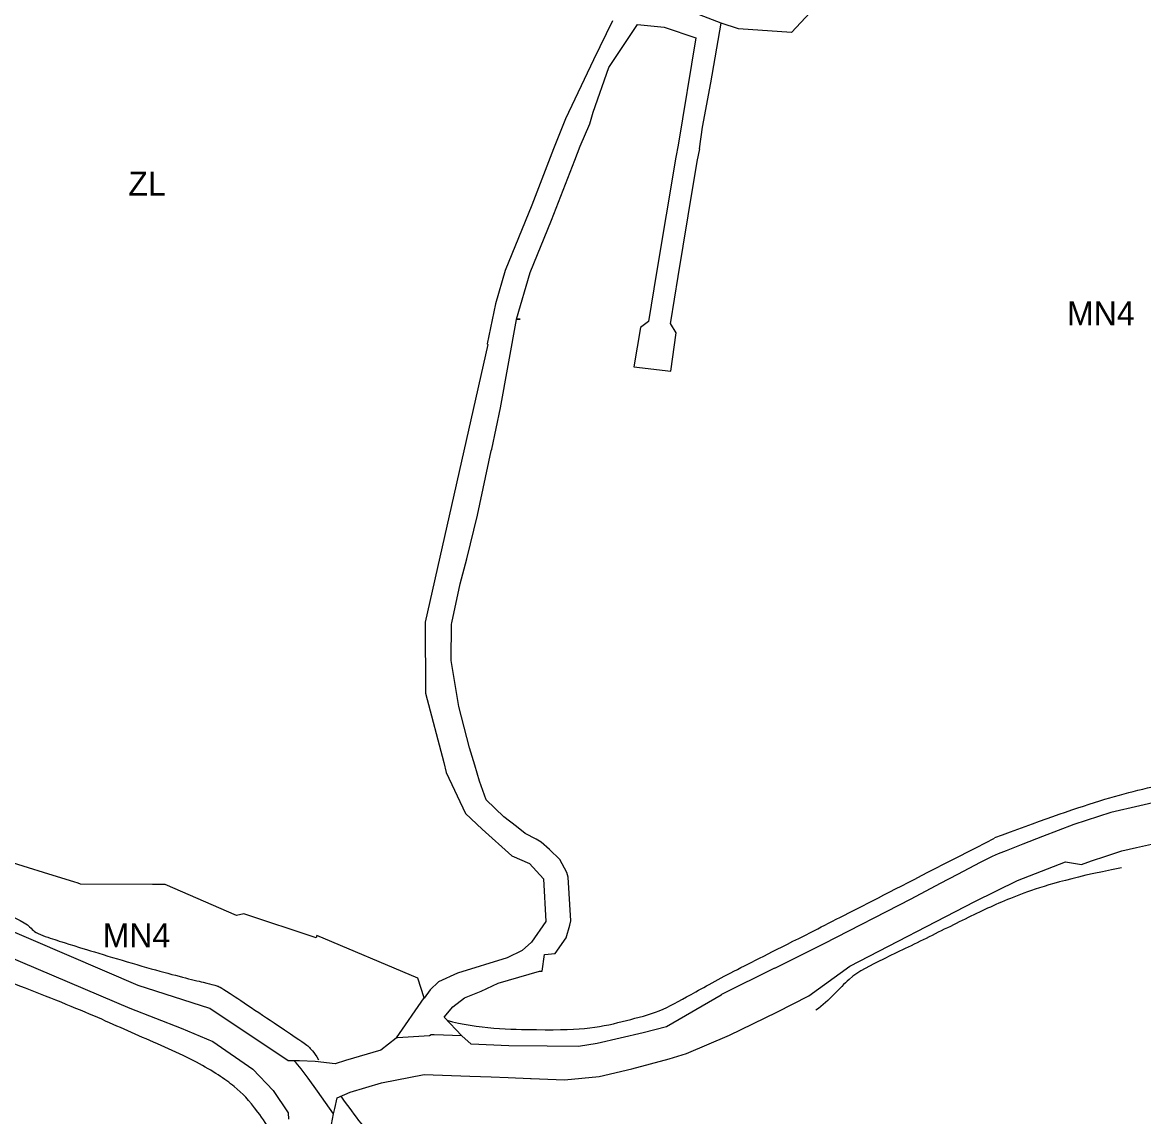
# Model space of a CAD drawing. Extents: x 7413438 to 7416393, y 5541665 to 5544118.
# Drawn here: x 7414980.3 to 7415261.6, y 5542694.9 to 5542969.5 of the extents above; entities that cross this region are included whole.
import ezdxf

# ---------------------------------------------------------------- set-up
doc = ezdxf.new("R2010")
doc.units = 0
for name, color, linetype in [('linie_rozgraniczajace', 7, 'Continuous'), ('linie_zabudowy_nieprzekraczalne', 7, 'Continuous'), ('oznaczenia_przeznaczen', 7, 'Continuous')]:
    doc.layers.add(name, color=color, linetype=linetype)

msp = doc.modelspace()

# ---------------------------------------------------------------- linework, layer by layer
at = {"layer": 'linie_rozgraniczajace'}
for p, q in [((7415185.78, 5542980.52), (7415173.2, 5542967.04)), ((7415155.59, 5542969.34), (7415150.15, 5542971.47)), ((7415128.31, 5542969.98), (7415123.55, 5542960.19)), ((7415127.37, 5542958.24), (7415134.6, 5542969.01)), ((7415134.6, 5542969.01), (7415141.25, 5542968.32)), ((7415153.02, 5542954.4), (7415155.59, 5542969.34)), ((7415159.9, 5542967.95), (7415155.59, 5542969.34)), ((7415141.25, 5542968.32), (7415149.22, 5542965.64)), ((7415149.22, 5542965.64), (7415144.76, 5542938.77)), ((7415173.2, 5542967.04), (7415159.9, 5542967.95)), ((7415123.55, 5542960.19), (7415116.57, 5542945.38)), ((7415123.44, 5542947.01), (7415127.37, 5542958.24)), ((7415150.88, 5542943.24), (7415153.02, 5542954.4)), ((7415122.65, 5542944.09), (7415123.44, 5542947.01)), ((7415116.57, 5542945.38), (7415113.51, 5542937.85)), ((7415120.17, 5542938.48), (7415122.65, 5542944.09)), ((7415150.12, 5542937.86), (7415150.88, 5542943.24)), ((7415113.51, 5542937.85), (7415108.05, 5542923.69)), ((7415118.84, 5542934.98), (7415120.17, 5542938.48)), ((7415144.76, 5542938.77), (7415144.25, 5542935.7)), ((7415149.58, 5542934.63), (7415150.2, 5542937.82)), ((7415150.22, 5542937.84), (7415150.12, 5542937.86)), ((7415150.2, 5542937.82), (7415150.22, 5542937.84)), ((7415112.99, 5542919.91), (7415118.84, 5542934.98)), ((7415144.25, 5542935.7), (7415139.39, 5542906.76)), ((7415147.33, 5542920.97), (7415149.59, 5542934.62)), ((7415149.59, 5542934.62), (7415149.58, 5542934.63)), ((7415108.05, 5542923.69), (7415101.43, 5542907.3)), ((7415144.82, 5542905.8), (7415147.33, 5542920.97)), ((7415107.7, 5542906.8), (7415112.99, 5542919.91)), ((7415101.43, 5542907.3), (7415098.99, 5542898.92)), ((7415104.26, 5542895.09), (7415107.7, 5542906.8)), ((7415139.39, 5542906.76), (7415137.32, 5542894.45)), ((7415142.93, 5542894.41), (7415144.82, 5542905.8)), ((7415098.99, 5542898.92), (7415096.89, 5542888.86)), ((7415100.21, 5542872.85), (7415104.23, 5542894.97)), ((7415104.23, 5542895.05), (7415104.26, 5542895.09)), ((7415105.14, 5542895.08), (7415104.23, 5542895.05)), ((7415104.23, 5542894.97), (7415105.14, 5542895.06)), ((7415105.14, 5542895.06), (7415105.14, 5542895.08)), ((7415135.31, 5542892.99), (7415133.64, 5542883.09)), ((7415137.32, 5542894.45), (7415135.31, 5542892.99)), ((7415142.85, 5542893.94), (7415142.93, 5542894.41)), ((7415144.27, 5542891.61), (7415142.85, 5542893.94)), ((7415142.97, 5542882), (7415144.27, 5542891.61)), ((7415097.01, 5542888.67), (7415081.3, 5542819.03)), ((7415096.89, 5542888.86), (7415097.01, 5542888.67)), ((7415133.64, 5542883.09), (7415142.97, 5542882)), ((7415098.01, 5542862.47), (7415100.21, 5542872.85)), ((7415094.45, 5542845.85), (7415097.92, 5542862.04)), ((7415097.92, 5542862.04), (7415098.01, 5542862.47)), ((7415091.78, 5542834.95), (7415094.45, 5542845.85)), ((7415090.12, 5542828.62), (7415091.79, 5542834.94)), ((7415091.79, 5542834.94), (7415091.78, 5542834.95)), ((7415087.98, 5542818.82), (7415090.12, 5542828.62)), ((7415081.3, 5542819.03), (7415081.37, 5542801.2)), ((7415087.83, 5542809.35), (7415087.93, 5542818.55)), ((7415087.93, 5542818.55), (7415087.98, 5542818.82)), ((7415089.79, 5542797.83), (7415087.83, 5542809.35)), ((7415081.37, 5542801.2), (7415085.97, 5542783.76)), ((7415092.43, 5542787.44), (7415089.79, 5542797.83)), ((7415093.75, 5542783.12), (7415092.43, 5542787.44)), ((7415085.97, 5542783.76), (7415086.62, 5542781.3)), ((7415094.97, 5542779.1), (7415093.75, 5542783.12)), ((7415086.62, 5542781.3), (7415091.45, 5542770.96)), ((7415096.66, 5542774.41), (7415094.97, 5542779.1)), ((7415101.02, 5542770.14), (7415096.66, 5542774.41)), ((7415277.94, 5542776.84), (7415253.36, 5542771.27)), ((7415091.45, 5542770.96), (7415095.65, 5542767.04)), ((7415104.2, 5542767.69), (7415101.02, 5542770.14)), ((7415253.36, 5542771.27), (7415244.08, 5542768.23)), ((7415095.65, 5542767.04), (7415103.08, 5542760.33)), ((7415106.44, 5542765.96), (7415104.2, 5542767.69)), ((7415109.14, 5542764.53), (7415106.44, 5542765.96)), ((7415244.08, 5542768.23), (7415236.24, 5542765.19)), ((7415110.46, 5542763.83), (7415109.14, 5542764.53)), ((7415112.53, 5542761.97), (7415110.46, 5542763.83)), ((7415231.3, 5542763.27), (7415227.06, 5542761.63)), ((7415236.24, 5542765.19), (7415231.3, 5542763.27)), ((7415259.77, 5542762.49), (7415263.52, 5542763.31)), ((7414986.87, 5542755.76), (7414967.03, 5542761.91)), ((7415103.08, 5542760.33), (7415107.52, 5542758.48)), ((7415115.12, 5542759.42), (7415112.53, 5542761.97)), ((7415225.12, 5542760.84), (7415223.55, 5542760.22)), ((7415225.78, 5542761.1), (7415225.12, 5542760.84)), ((7415227.06, 5542761.61), (7415225.78, 5542761.1)), ((7415227.06, 5542761.63), (7415227.06, 5542761.61)), ((7415248.48, 5542759.07), (7415252.08, 5542760.3)), ((7415252.08, 5542760.3), (7415256.09, 5542761.59)), ((7415256.09, 5542761.59), (7415259.77, 5542762.49)), ((7415107.52, 5542758.48), (7415111.03, 5542754.63)), ((7415116.9, 5542756.17), (7415115.12, 5542759.42)), ((7415220.59, 5542758.68), (7415214.9, 5542755.72)), ((7415223.55, 5542760.22), (7415220.59, 5542758.68)), ((7415229.96, 5542754.18), (7415241.99, 5542758.83)), ((7415241.99, 5542758.83), (7415245.97, 5542758.23)), ((7415245.97, 5542758.23), (7415248.48, 5542759.07)), ((7414993.14, 5542753.81), (7414986.87, 5542755.76)), ((7415111.03, 5542754.63), (7415111.63, 5542743.84)), ((7415117.19, 5542755.04), (7415116.9, 5542756.17)), ((7415117.88, 5542744.02), (7415117.19, 5542755.04)), ((7415214.9, 5542755.72), (7415210.52, 5542753.44)), ((7415214.9, 5542755.72), (7415214.9, 5542755.72)), ((7414994.22, 5542753.48), (7414993.14, 5542753.81)), ((7414994.83, 5542753.28), (7414994.22, 5542753.48)), ((7415012.92, 5542753.17), (7414994.83, 5542753.28)), ((7415016.1, 5542753.15), (7415012.92, 5542753.17)), ((7415033.95, 5542745.35), (7415016.1, 5542753.15)), ((7415210.52, 5542753.44), (7415203.14, 5542749.45)), ((7415219.21, 5542748.94), (7415229.96, 5542754.18)), ((7415009.32, 5542727.85), (7414958.64, 5542749.51)), ((7415203.14, 5542749.49), (7415181.33, 5542738.3)), ((7415203.14, 5542749.45), (7415203.14, 5542749.49)), ((7415187.9, 5542732.66), (7415219.21, 5542748.94)), ((7415035.82, 5542745.84), (7415033.95, 5542745.35)), ((7415053.98, 5542739.77), (7415035.82, 5542745.84)), ((7415111.63, 5542743.84), (7415107.98, 5542738.68)), ((7415117.59, 5542742.93), (7415117.88, 5542744.02)), ((7415116.72, 5542739.76), (7415117.59, 5542742.93)), ((7415054.13, 5542740.34), (7415053.98, 5542739.77)), ((7415079.48, 5542729.7), (7415054.13, 5542740.34)), ((7415107.98, 5542738.68), (7415105.66, 5542736.59)), ((7415113.9, 5542735.86), (7415116.72, 5542739.76)), ((7415181.33, 5542738.27), (7415169, 5542732.08)), ((7415181.33, 5542738.3), (7415181.33, 5542738.27)), ((7414976.34, 5542735.27), (7415007.22, 5542722.13)), ((7415105.66, 5542736.59), (7415101.88, 5542734.73)), ((7415110.69, 5542731.43), (7415111.26, 5542735.64)), ((7415111.26, 5542735.64), (7415113.9, 5542735.86)), ((7415101.88, 5542734.73), (7415089.47, 5542730.9)), ((7415169, 5542732.14), (7415155.67, 5542725.54)), ((7415169, 5542732.08), (7415169, 5542732.14)), ((7415177.56, 5542725.2), (7415187.9, 5542732.66)), ((7415081.05, 5542724.71), (7415079.48, 5542729.7)), ((7415089.47, 5542730.9), (7415084.7, 5542728.72)), ((7415099.67, 5542728.37), (7415110.01, 5542731.4)), ((7415110.01, 5542731.4), (7415110.69, 5542731.43)), ((7415027.31, 5542722.08), (7415009.32, 5542727.85)), ((7415082.55, 5542726.74), (7415081.07, 5542724.67)), ((7415084.7, 5542728.72), (7415082.55, 5542726.74)), ((7415095.33, 5542726.36), (7415099.67, 5542728.37)), ((7415074.14, 5542714.71), (7415081.05, 5542724.71)), ((7415081.07, 5542724.67), (7415081.05, 5542724.71)), ((7415088.22, 5542722.48), (7415091.2, 5542724.71)), ((7415091.2, 5542724.71), (7415095.33, 5542726.36)), ((7415155.59, 5542725.42), (7415141.89, 5542717.46)), ((7415155.67, 5542725.54), (7415155.59, 5542725.5)), ((7415155.59, 5542725.5), (7415155.59, 5542725.42)), ((7415169.52, 5542721.15), (7415177.56, 5542725.2)), ((7415007.22, 5542722.13), (7415020.11, 5542717.14)), ((7415046.98, 5542708.87), (7415027.31, 5542722.08)), ((7415086.05, 5542719.85), (7415088.22, 5542722.48)), ((7415157.68, 5542715.32), (7415169.52, 5542721.15)), ((7415090.55, 5542715.15), (7415086.05, 5542719.85)), ((7415020.11, 5542717.14), (7415028.01, 5542713.75)), ((7415082.8, 5542715.44), (7415082.41, 5542715.21)), ((7415083.61, 5542715.41), (7415082.8, 5542715.44)), ((7415090.55, 5542715.15), (7415083.61, 5542715.41)), ((7415136.01, 5542715.94), (7415124.51, 5542713.25)), ((7415141.89, 5542717.46), (7415136.01, 5542715.94)), ((7415146.92, 5542710.77), (7415157.68, 5542715.32)), ((7415028.01, 5542713.75), (7415038.11, 5542706.82)), ((7415074.08, 5542714.63), (7415070.21, 5542711.62)), ((7415074.14, 5542714.71), (7415074.08, 5542714.63)), ((7415074.36, 5542714.7), (7415074.14, 5542714.71)), ((7415082.41, 5542715.21), (7415074.36, 5542714.7)), ((7415092.85, 5542713.07), (7415090.55, 5542715.15)), ((7415102.35, 5542712.71), (7415092.85, 5542713.07)), ((7415111.95, 5542712.57), (7415102.35, 5542712.71)), ((7415119.82, 5542712.52), (7415111.95, 5542712.57)), ((7415124.51, 5542713.25), (7415119.82, 5542712.52)), ((7415070.21, 5542711.62), (7415061.36, 5542709.02)), ((7415142.55, 5542709.44), (7415146.92, 5542710.77)), ((7415038.11, 5542706.82), (7415043.19, 5542701.48)), ((7415048.45, 5542708.94), (7415046.98, 5542708.87)), ((7415048.97, 5542708.37), (7415048.45, 5542708.94)), ((7415049.74, 5542708.88), (7415048.45, 5542708.94)), ((7415050.23, 5542706.91), (7415048.97, 5542708.37)), ((7415049.75, 5542708.87), (7415049.74, 5542708.88)), ((7415053.7, 5542708.74), (7415049.75, 5542708.87)), ((7415051.97, 5542704.57), (7415050.23, 5542706.91)), ((7415058.75, 5542708.12), (7415053.7, 5542708.74)), ((7415061.36, 5542709.02), (7415058.75, 5542708.12)), ((7415125.01, 5542705.01), (7415133.14, 5542706.93)), ((7415133.14, 5542706.93), (7415142.58, 5542709.4)), ((7415142.58, 5542709.4), (7415142.55, 5542709.44)), ((7415054.3, 5542701.33), (7415051.97, 5542704.57)), ((7415070.34, 5542703.4), (7415081.04, 5542705.5)), ((7415081.04, 5542705.5), (7415092.55, 5542705.07)), ((7415092.55, 5542705.07), (7415097.91, 5542704.87)), ((7415097.91, 5542704.87), (7415102.18, 5542704.71)), ((7415102.18, 5542704.71), (7415107.75, 5542704.5)), ((7415107.75, 5542704.5), (7415107.95, 5542704.5)), ((7415107.95, 5542704.5), (7415116.29, 5542704.18)), ((7415116.29, 5542704.18), (7415125.01, 5542705.01)), ((7415043.19, 5542701.48), (7415046.96, 5542695.83)), ((7415058.35, 5542695.59), (7415054.3, 5542701.33)), ((7415062.46, 5542701.01), (7415070.34, 5542703.4)), ((7415058.65, 5542696.98), (7415059.22, 5542699.64)), ((7415059.22, 5542699.64), (7415062.46, 5542701.01)), ((7415046.96, 5542695.83), (7415047.02, 5542694.24)), ((7415057.85, 5542692.95), (7415058.35, 5542695.59)), ((7415058.35, 5542695.59), (7415058.65, 5542696.98))]:
    msp.add_line(p, q, dxfattribs=at)
at = {"layer": 'linie_zabudowy_nieprzekraczalne'}
for points in [[(7415224.24, 5542764.93), (7415234.87, 5542768.93), (7415252.45, 5542775.15), (7415267.62, 5542778.59), (7415300.4, 5542786.16), (7415306.31, 5542787.89), (7415321.64, 5542794.04), (7415341.99, 5542803.09), (7415373.83, 5542816.66), (7415358.63, 5542848.96), (7415349.07, 5542869.68), (7415324.44, 5542923.07), (7415321.98, 5542928.69), (7415321.86, 5542932.66), (7415323.07, 5542937.93), (7415326.67, 5542952.06), (7415325.97, 5542960.66), (7415326.79, 5542972.64), (7415328.33, 5542984.95), (7415330.18, 5542999.75), (7415333.24, 5543013.48), (7415339.07, 5543034.4), (7415348.26, 5543068.35), (7415353.84, 5543088.85), (7415355.35, 5543096.84)], [(7415046.04, 5542685.6), (7415044.89, 5542688.05), (7415038.46, 5542697.69), (7415034.17, 5542702.2), (7415025.08, 5542708.44), (7415009, 5542715.33), (7414995.57, 5542721.52), (7414970.94, 5542731.05), (7414970.88, 5542731.08), (7414970.52, 5542731.25), (7414970.35, 5542731.34), (7414938.93, 5542744.38), (7414938.9, 5542744.39), (7414938.71, 5542744.46), (7414901.8, 5542759.46), (7414901.63, 5542759.53), (7414901.27, 5542759.7), (7414900.93, 5542759.89), (7414900.6, 5542760.11), (7414900.45, 5542760.22), (7414898.5, 5542761.69), (7414898.34, 5542761.82), (7414898.1, 5542762.02), (7414893.84, 5542765.85), (7414883.77, 5542771.83), (7414883.71, 5542771.87), (7414883.61, 5542771.93), (7414880.89, 5542773.67), (7414878.59, 5542776.46), (7414860.73, 5542786.52), (7414855.46, 5542791.34), (7414852.65, 5542792.67), (7414844.32, 5542798.84), (7414832.02, 5542808.01), (7414822.28, 5542811.7), (7414810.95, 5542816.79), (7414794.96, 5542824.01), (7414775.51, 5542832.34), (7414755.97, 5542839.09), (7414752.31, 5542840.07), (7414750.38, 5542840.58), (7414740.26, 5542842.54), (7414740.13, 5542842.57), (7414739.26, 5542842.76)], [(7414894.41, 5542785.03), (7414903.96, 5542777.18), (7414916.18, 5542770.19), (7414940, 5542760.98), (7414955.95, 5542754.25), (7414982.82, 5542743.43), (7414982.18, 5542741.35), (7414988.41, 5542739.33), (7414991.26, 5542738.4), (7415014.09, 5542731.42), (7415027.59, 5542728.16), (7415029.35, 5542727.68), (7415030.41, 5542727.17), (7415050.65, 5542713.59), (7415051.96, 5542712.68), (7415053.26, 5542711.22), (7415054.57, 5542709.16)], [(7415086.74, 5542719.08), (7415094.43, 5542716.98), (7415111.6, 5542716.62), (7415123.06, 5542716.83), (7415131.88, 5542719.06), (7415140.33, 5542721.17), (7415147.23, 5542725.18), (7415159.02, 5542731.64), (7415174.62, 5542739.36), (7415199.13, 5542751.92), (7415224.18, 5542764.82)], [(7415255.99, 5542757.33), (7415242.42, 5542754.69), (7415230.19, 5542750.76), (7415220.02, 5542746.15), (7415207.74, 5542739.98), (7415195.65, 5542734.12), (7415187.52, 5542730.25), (7415182.85, 5542724.07), (7415179.34, 5542721.6)], [(7415060.2, 5542700.03), (7415063.8, 5542694.82), (7415069.96, 5542687.2), (7415074.97, 5542682.48), (7415094.07, 5542670.45), (7415095.67, 5542670.19), (7415115.82, 5542663.31), (7415160.33, 5542649.35), (7415173.61, 5542643.76), (7415176.31, 5542642.11), (7415190.15, 5542632.51), (7415210.39, 5542618.3), (7415230.16, 5542603.31), (7415243.83, 5542592.3), (7415246.54, 5542589.46), (7415257.35, 5542580.95), (7415265.92, 5542574.94), (7415271.31, 5542571.58), (7415279.78, 5542563.89), (7415291.54, 5542557.48)]]:
    msp.add_open_spline(points, degree=3, dxfattribs=at)

# ---------------------------------------------------------------- texts
at = {"layer": 'oznaczenia_przeznaczen'}
for s, p in [('ZL', (7415006.85, 5542926.09)), ('MN4', (7415242.37, 5542893.54)), ('MN4', (7415000.41, 5542737.4))]:
    msp.add_text(s, height=6, dxfattribs=at).set_placement(p)

doc.saveas('drawing.dxf')
